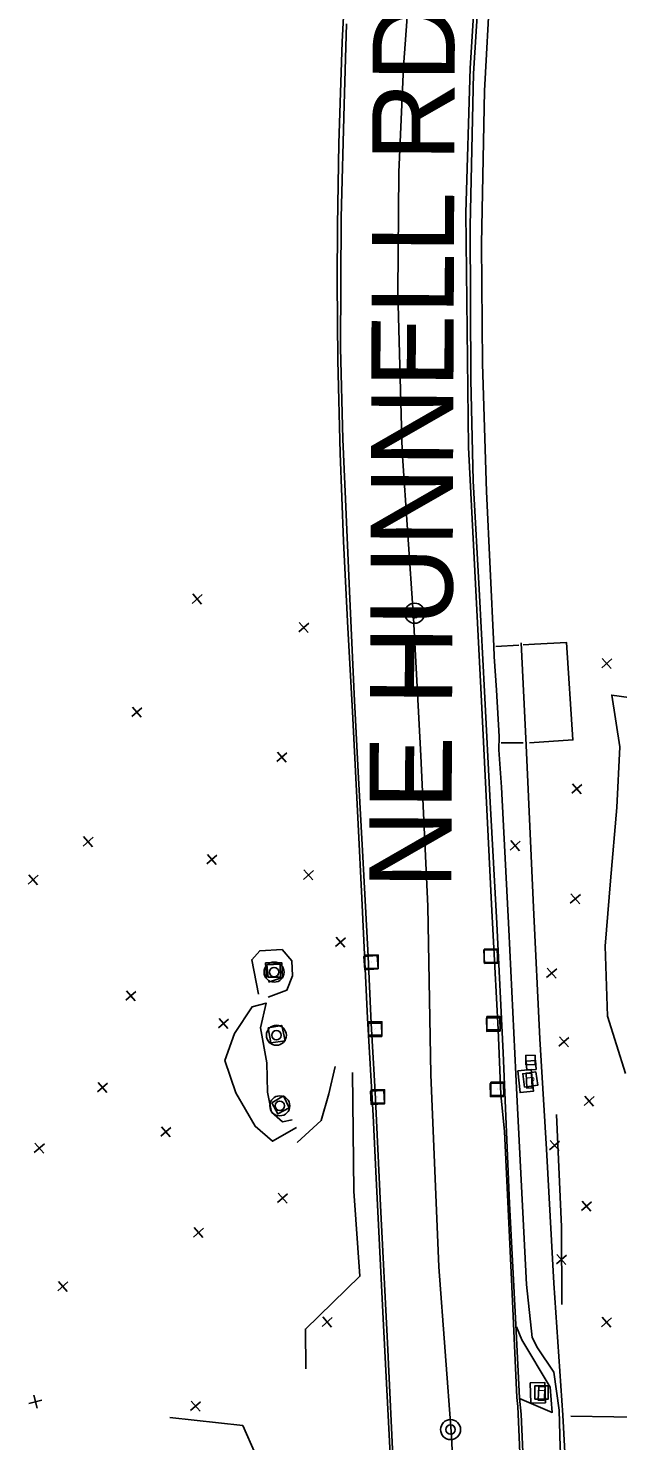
# Model space of a CAD drawing. Extents: x 4711259 to 4716401, y 890074 to 892728.
# Drawn here: x 4711924 to 4712145, y 891910 to 892439 of the extents above; entities that cross this region are included whole.
import ezdxf

# ---------------------------------------------------------------- set-up
doc = ezdxf.new("R2010")
doc.units = 0
for name, color, linetype in [('E_HY_STORM_Inlet', 7, 'Continuous'), ('E_HY_STORM_MH', 7, 'Continuous'), ('E_RDWY_ROAD_Curb', 7, 'Continuous'), ('E_RDWY_ROAD_EdgeAsph', 7, 'Continuous'), ('E_RDWY_ROAD_EdgeConc', 7, 'Continuous'), ('E_RDWY_ROAD_Fence', 7, 'Continuous'), ('E_RDWY_ROAD_NameTx', 7, 'Continuous'), ('E_RDWY_ROAD_Sidewalk', 7, 'Continuous'), ('E_RDWY_ROAD_TBofCurb', 7, 'Continuous'), ('E_TERR_DTM_BrkLines', 7, 'Continuous'), ('E_TERR_DTM_RandomPt', 7, 'Continuous'), ('E_UTIL_COMM_General', 7, 'Continuous'), ('E_UTIL_ELEC_GENERAL', 7, 'Continuous'), ('E_UTIL_MISC_General', 7, 'Continuous')]:
    doc.layers.add(name, color=color, linetype=linetype)

msp = doc.modelspace()

# ---------------------------------------------------------------- linework, layer by layer
at = {"layer": 'E_HY_STORM_Inlet'}
for p, q in [((4712052.79, 892089.27), (4712052.79, 892089.27)), ((4712097.57, 892091.4), (4712097.57, 892091.4)), ((4712097.57, 892091.12), (4712097.57, 892091.12)), ((4712052.61, 892088.88), (4712052.61, 892088.88)), ((4712054.05, 892063.69), (4712054.05, 892063.69)), ((4712054.15, 892064.24), (4712054.15, 892064.24)), ((4712098.51, 892065.66), (4712098.51, 892065.66)), ((4712098.54, 892066.2), (4712098.54, 892066.2)), ((4712100.01, 892041.58), (4712100.01, 892041.58)), ((4712055, 892038.34), (4712055, 892038.34)), ((4712055.17, 892038.73), (4712055.17, 892038.73)), ((4712099.88, 892041.17), (4712099.88, 892041.17))]:
    msp.add_line(p, q, dxfattribs=at)
for points in [[(4712055.26, 892086.54), (4712050.27, 892086.22), (4712049.95, 892091.21), (4712054.94, 892091.53)], [(4712050.3, 892091.78), (4712055.3, 892091.76), (4712055.28, 892086.76), (4712050.28, 892086.78)], [(4712095.16, 892088.54), (4712094.98, 892093.53), (4712099.97, 892093.71), (4712100.15, 892088.72)], [(4712095.08, 892093.91), (4712100.08, 892093.89), (4712100.06, 892088.89), (4712095.06, 892088.91)], [(4712101.04, 892063.19), (4712096.04, 892063.13), (4712095.97, 892068.13), (4712100.97, 892068.19)], [(4712096.06, 892068.71), (4712101.06, 892068.68), (4712101.03, 892063.68), (4712096.03, 892063.71)], [(4712056.63, 892061.27), (4712051.63, 892061.11), (4712051.47, 892066.11), (4712056.47, 892066.27)], [(4712051.66, 892066.75), (4712056.66, 892066.73), (4712056.63, 892061.73), (4712051.63, 892061.75)], [(4712102.45, 892038.74), (4712097.45, 892038.6), (4712097.31, 892043.6), (4712102.31, 892043.74)], [(4712097.52, 892044.1), (4712102.52, 892044.07), (4712102.5, 892039.07), (4712097.5, 892039.1)], [(4712057.38, 892040.95), (4712057.61, 892035.95), (4712052.61, 892035.73), (4712052.39, 892040.72)], [(4712052.68, 892041.24), (4712057.68, 892041.22), (4712057.66, 892036.22), (4712052.66, 892036.24)]]:
    msp.add_lwpolyline(points, close=True, dxfattribs=at)
at = {"layer": 'E_HY_STORM_MH'}
for centre, radius in [((4712068.96, 892219.89), 3.75), ((4712068.96, 892219.89), 1.76), ((4712016.22, 892085.34), 3.75), ((4712016.22, 892085.34), 1.76), ((4712017.07, 892061.67), 3.75), ((4712017.07, 892061.67), 1.76), ((4712018.36, 892035.23), 3.75), ((4712018.36, 892035.23), 1.76), ((4712082.43, 891913.85), 3.75), ((4712082.43, 891913.85), 1.76)]:
    msp.add_circle(centre, radius, dxfattribs=at)
at = {"layer": 'E_RDWY_ROAD_Curb'}
for points in [[(4712099.18, 892547.25), (4712096.65, 892523.49), (4712093.14, 892478.19), (4712089.84, 892424.15), (4712088.13, 892369.91), (4712089.13, 892281.96), (4712093.91, 892189.39), (4712097.79, 892110.85), (4712100.26, 892063.89), (4712101.34, 892039.44)], [(4712061.12, 891895.88), (4712058.81, 891946.36), (4712056.1, 891997.86), (4712054.08, 892040.38), (4712052.64, 892066.08), (4712051.5, 892091.2), (4712049.49, 892128.59), (4712047.81, 892160.4), (4712046.24, 892189.6), (4712044.57, 892228.09), (4712042.97, 892262.59), (4712041.98, 892285.1), (4712041.16, 892319.32), (4712041.36, 892368.18), (4712042.48, 892410.46), (4712043.41, 892440.81)], [(4712108.95, 891893.59), (4712107.64, 891922.46), (4712107.35, 891925.85), (4712105.45, 891967.55), (4712102.66, 892025.6), (4712101.34, 892039.44)]]:
    msp.add_lwpolyline(points, dxfattribs=at)
at = {"layer": 'E_RDWY_ROAD_EdgeAsph'}
for points in [[(4712099.46, 892207.4), (4712108.04, 892207.91)], [(4712109.7, 892208.01), (4712113.9, 892208.26), (4712125.93, 892208.94), (4712128.37, 892172.41), (4712112.11, 892171.28)], [(4712109.71, 892171.29), (4712101.42, 892171.33)], [(4712266.21, 891916.53), (4712212.37, 891917.36), (4712159.79, 891918.41), (4712127.55, 891918.93)]]:
    msp.add_lwpolyline(points, dxfattribs=at)
at = {"layer": 'E_RDWY_ROAD_EdgeConc'}
for points in [[(4712018.62, 892083.49), (4712018.44, 892088.3), (4712013.48, 892088.02), (4712013.98, 892083.51)], [(4712013.98, 892083.51), (4712018.62, 892083.49)], [(4712014.04, 892064.47), (4712019.11, 892065.36), (4712020.31, 892059.57), (4712014.94, 892058.81), (4712014.04, 892064.47)], [(4712015.42, 892036.35), (4712019.72, 892038.96), (4712021.91, 892034.5), (4712017.58, 892032.25), (4712015.42, 892036.35)]]:
    msp.add_lwpolyline(points, dxfattribs=at)
for points in [[(4712107.68, 892048.29), (4712112.72, 892048.79), (4712113.52, 892040.66), (4712108.49, 892040.16)], [(4712118.01, 891923.92), (4712117.8, 891931.52), (4712112.31, 891931.37), (4712112.52, 891923.76)]]:
    msp.add_lwpolyline(points, close=True, dxfattribs=at)
at = {"layer": 'E_RDWY_ROAD_Fence'}
msp.add_lwpolyline([(4712128.59, 891451.64), (4712127.77, 891481.95), (4712127.92, 891531.97), (4712127.41, 891562.39), (4712127.6, 891590.09), (4712127.3, 891649.86), (4712127.17, 891700.22), (4712128.2, 891710.35), (4712134.44, 891739.35), (4712132.91, 891765.97), (4712132.02, 891783.01), (4712129.51, 891829.8), (4712126.66, 891879.73), (4712124.56, 891919.3), (4712121.22, 891968.8), (4712118.38, 892019.02), (4712115.97, 892060.36), (4712113.52, 892109.62), (4712110.82, 892170.44), (4712108.89, 892208.75)], dxfattribs=at)
at = {"layer": 'E_RDWY_ROAD_Sidewalk'}
for points in [[(4712107.29, 892039.34), (4712104.25, 892101.38), (4712101.53, 892154.64), (4712100.59, 892168.61), (4712100.62, 892173.73), (4712099.69, 892191.03), (4712098.8, 892203.61), (4712098.66, 892207.49), (4712095.89, 892265.57), (4712094.39, 892313.37), (4712094.07, 892358.35), (4712095.2, 892415.65), (4712097.31, 892454.84), (4712098.14, 892465.16), (4712099.68, 892486.45), (4712100.33, 892494.24), (4712102.85, 892518.82), (4712107.37, 892565.05), (4712113.06, 892611.48), (4712114.88, 892620.3), (4712116.68, 892623.04), (4712119.52, 892625.47), (4712122.93, 892626.66), (4712138.98, 892627.38)], [(4712107.29, 892039.34), (4712110.95, 891968.19), (4712113.05, 891948.39), (4712115.09, 891944.48), (4712121.14, 891935.44)], [(4712108.35, 891925.49), (4712120.58, 891920.28), (4712119.87, 891929.75), (4712109.12, 891947.52), (4712107.13, 891952.43)], [(4712126.93, 891858.21), (4712124.51, 891893.18), (4712123.61, 891907.21), (4712123.16, 891921.16), (4712121.14, 891935.44)]]:
    msp.add_lwpolyline(points, dxfattribs=at)
at = {"layer": 'E_RDWY_ROAD_TBofCurb'}
for points in [[(4712061.59, 891856.07), (4712059.6, 891907), (4712057.19, 891955.42), (4712054.44, 892010.61), (4712053.34, 892031.64), (4712051.25, 892068.13), (4712049.2, 892113.04), (4712047.82, 892140.76), (4712045.61, 892182.95), (4712043.81, 892216.79), (4712042.32, 892246.93), (4712041, 892279.84), (4712040.18, 892314.64), (4712039.84, 892344.38), (4712039.97, 892365.28), (4712040.56, 892395.97), (4712041.8, 892434.04), (4712043.17, 892460.21), (4712046.81, 892511.51), (4712051.22, 892555.82), (4712054.06, 892580.06), (4712058.44, 892615.38), (4712068.17, 892688.61), (4712073.12, 892727.49)], [(4712110.1, 891894.08), (4712108.88, 891919.59), (4712108.24, 891925.65), (4712106.92, 891953.24), (4712104.61, 891998.58), (4712102.13, 892055.12), (4712099.76, 892103.59), (4712097.28, 892149.01), (4712095.13, 892190.52), (4712093.23, 892226.55), (4712090.92, 892269.45), (4712090.01, 892307.31), (4712089.8, 892365.13), (4712091.06, 892422.26), (4712094.26, 892473.51)]]:
    msp.add_lwpolyline(points, dxfattribs=at)
at = {"layer": 'E_TERR_DTM_BrkLines'}
for points in [[(4712084.93, 891866.74), (4712082.77, 891911.45), (4712077.99, 891974.82), (4712075.09, 892046.95), (4712073.94, 892110.06), (4712071.33, 892166.44), (4712068.53, 892218.19), (4712064.26, 892280.69), (4712062.66, 892340.12), (4712062.96, 892385.2), (4712064.73, 892424.66), (4712068.8, 892479.3), (4712075.74, 892554.89), (4712077.15, 892572.62)], [(4712148.04, 892047.33), (4712141.36, 892068.82), (4712140.51, 892095.04), (4712142.48, 892119.54), (4712144.82, 892147.01), (4712145.96, 892169.74), (4712142.91, 892189.2), (4712155.65, 892187.47)], [(4712010.41, 892077.1), (4712007.86, 892089.99), (4712010.85, 892093.33), (4712019.23, 892093.77), (4712022.91, 892089.55), (4712023.06, 892083.97), (4712021.02, 892078.53), (4712013.99, 892075.99)], [(4712013.33, 892083.22), (4712013.01, 892088.78), (4712019.09, 892088.87), (4712019.4, 892083.28), (4712014.16, 892081.62)], [(4712024.68, 892027.13), (4712015.63, 892021.93), (4712009.1, 892027.57), (4712001.8, 892040.12), (4711997.71, 892052.2), (4712001.37, 892062.38), (4712008.04, 892072.38), (4712013.21, 892073.73), (4712011.14, 892064.44), (4712013.48, 892051.28), (4712013.77, 892040.29), (4712015.22, 892032.86), (4712019.33, 892029.2), (4712023.05, 892029.98)], [(4712039.09, 892049.97), (4712036.76, 892039.68), (4712033.86, 892029.77), (4712024.82, 892021.53)], [(4712045.62, 892047.73), (4712046.13, 892003.17), (4712048.42, 891971.36), (4712027.98, 891951.52), (4712028.12, 891936.57)], [(4712122.14, 892032.01), (4712124.07, 891989.81), (4712124.19, 891960.81)], [(4711977.06, 891918.45), (4712004.45, 891915.43), (4712018.38, 891883.87), (4712020.3, 891872.09)]]:
    msp.add_lwpolyline(points, dxfattribs=at)
at = {"layer": 'E_TERR_DTM_RandomPt'}
for p, q in [((4711989.27, 892226.86), (4711985.5, 892223.56)), ((4711989.03, 892223.33), (4711985.74, 892227.09)), ((4712029.2, 892216.17), (4712025.44, 892212.88)), ((4712028.96, 892212.64), (4712025.67, 892216.41)), ((4712142.91, 892202.74), (4712139.14, 892199.45)), ((4712142.67, 892199.21), (4712139.38, 892202.97)), ((4711966.55, 892184.46), (4711962.78, 892181.17)), ((4711966.31, 892180.93), (4711963.02, 892184.7)), ((4712020.98, 892167.6), (4712017.22, 892164.3)), ((4712020.75, 892164.07), (4712017.46, 892167.83)), ((4712131.7, 892155.7), (4712127.93, 892152.41)), ((4712131.46, 892152.17), (4712128.17, 892155.94)), ((4711948.27, 892135.9), (4711944.51, 892132.61)), ((4711948.04, 892132.37), (4711944.74, 892136.13)), ((4712108.56, 892134.39), (4712104.8, 892131.1)), ((4712108.33, 892130.86), (4712105.04, 892134.63)), ((4711994.77, 892129.2), (4711991, 892125.9)), ((4711994.53, 892125.67), (4711991.24, 892129.43)), ((4711927.71, 892121.63), (4711923.95, 892118.34)), ((4711927.48, 892118.1), (4711924.19, 892121.86)), ((4712030.96, 892123.41), (4712027.19, 892120.12)), ((4712030.72, 892119.88), (4712027.43, 892123.65)), ((4712131.13, 892114.46), (4712127.37, 892111.17)), ((4712130.89, 892110.93), (4712127.6, 892114.69)), ((4712043.05, 892098.24), (4712039.29, 892094.95)), ((4712042.81, 892094.71), (4712039.52, 892098.48)), ((4712122.25, 892086.61), (4712118.48, 892083.32)), ((4712122.01, 892083.09), (4712118.72, 892086.85)), ((4711964.32, 892078.08), (4711960.56, 892074.78)), ((4711964.08, 892074.55), (4711960.79, 892078.31)), ((4711998.84, 892064.22), (4711995.55, 892067.99)), ((4711999.08, 892067.75), (4711995.31, 892064.46)), ((4712126.87, 892060.86), (4712123.11, 892057.57)), ((4712126.63, 892057.33), (4712123.34, 892061.1)), ((4711953.73, 892043.71), (4711949.97, 892040.41)), ((4711953.49, 892040.18), (4711950.2, 892043.94)), ((4712136.32, 892038.66), (4712132.55, 892035.37)), ((4712136.08, 892035.14), (4712132.79, 892038.9)), ((4711977.45, 892027.09), (4711973.69, 892023.8)), ((4711977.21, 892023.56), (4711973.92, 892027.33)), ((4711930.01, 892021.02), (4711926.24, 892017.73)), ((4711929.77, 892017.5), (4711926.48, 892021.26)), ((4712123.37, 892021.98), (4712119.6, 892018.68)), ((4712123.13, 892018.45), (4712119.84, 892022.21)), ((4712021.3, 892002.28), (4712017.54, 891998.98)), ((4712021.07, 891998.75), (4712017.78, 892002.51)), ((4712135.34, 891999.25), (4712131.57, 891995.96)), ((4712135.1, 891995.73), (4712131.81, 891999.49)), ((4711989.7, 891989.34), (4711985.93, 891986.05)), ((4711989.46, 891985.81), (4711986.17, 891989.58)), ((4712125.89, 891979.27), (4712122.13, 891975.98)), ((4712125.65, 891975.74), (4712122.36, 891979.51)), ((4711938.79, 891969.19), (4711935.03, 891965.9)), ((4711938.55, 891965.66), (4711935.26, 891969.43)), ((4712038.02, 891955.83), (4712034.26, 891952.54)), ((4712037.78, 891952.3), (4712034.49, 891956.07)), ((4712142.82, 891955.71), (4712139.05, 891952.42)), ((4712142.58, 891952.19), (4712139.29, 891955.95)), ((4711924.22, 891923.66), (4711929.06, 891924.93)), ((4711927.27, 891921.88), (4711926, 891926.71)), ((4711988.65, 891924.29), (4711984.89, 891921)), ((4711988.41, 891920.76), (4711985.12, 891924.52))]:
    msp.add_line(p, q, dxfattribs=at)
at = {"layer": 'E_UTIL_COMM_General'}
for points in [[(4712114.17, 892050.65), (4712110.67, 892050.67), (4712110.69, 892054.17), (4712114.19, 892054.15)], [(4712114.59, 892048.78), (4712111.1, 892048.53), (4712110.86, 892052.02), (4712114.35, 892052.27)]]:
    msp.add_lwpolyline(points, close=True, dxfattribs=at)
at = {"layer": 'E_UTIL_ELEC_GENERAL'}
for points in [[(4712114.48, 892047.91), (4712115.15, 892042.95), (4712110.19, 892042.28), (4712109.52, 892047.24)], [(4712119.11, 891930.27), (4712119.09, 891925.27), (4712114.09, 891925.3), (4712114.11, 891930.3)]]:
    msp.add_lwpolyline(points, close=True, dxfattribs=at)
at = {"layer": 'E_UTIL_MISC_General'}
for points in [[(4712113.04, 892041.96), (4712111.01, 892041.88), (4712110.79, 892047.43), (4712112.82, 892047.51)], [(4712117.6, 891924.77), (4712115.26, 891924.93), (4712115.6, 891930.04), (4712117.94, 891929.88)]]:
    msp.add_lwpolyline(points, close=True, dxfattribs=at)

# ---------------------------------------------------------------- texts
at = {"layer": 'E_RDWY_ROAD_NameTx'}
msp.add_text('NE HUNNELL RD.', height=30.8399, rotation=89.7618, dxfattribs=at).set_placement((4712082.73, 892116.46))
at = {"layer": 'E_UTIL_ELEC_GENERAL'}
for rotation, p in [(97.6826, (4712114, 892044.47)), (89.7251, (4712118.17, 891926.93))]:
    msp.add_text('J', height=3, rotation=rotation, dxfattribs=at).set_placement(p)

doc.saveas('drawing.dxf')
